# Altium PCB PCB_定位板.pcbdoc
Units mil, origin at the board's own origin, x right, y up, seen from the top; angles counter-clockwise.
Board outline 4260 x 2380 mil, 2 copper layers (Top Layer, Bottom Layer), stack 2.757 mil thick; 2 components, 2 nets, 2 pads, 2 vias.
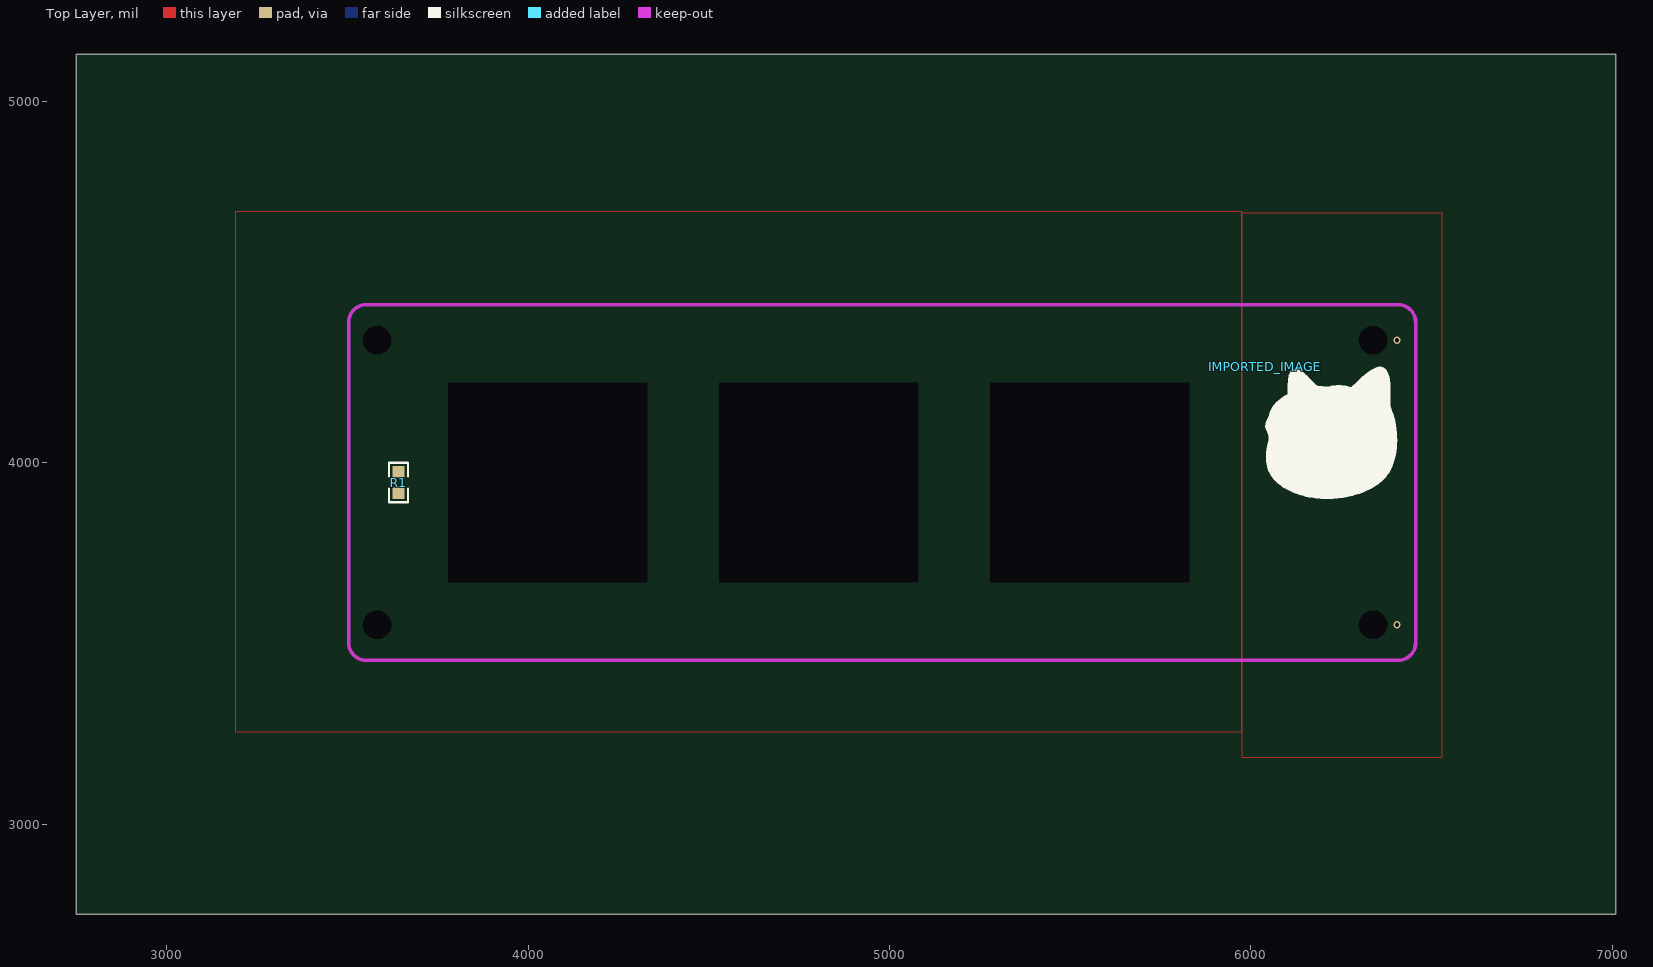
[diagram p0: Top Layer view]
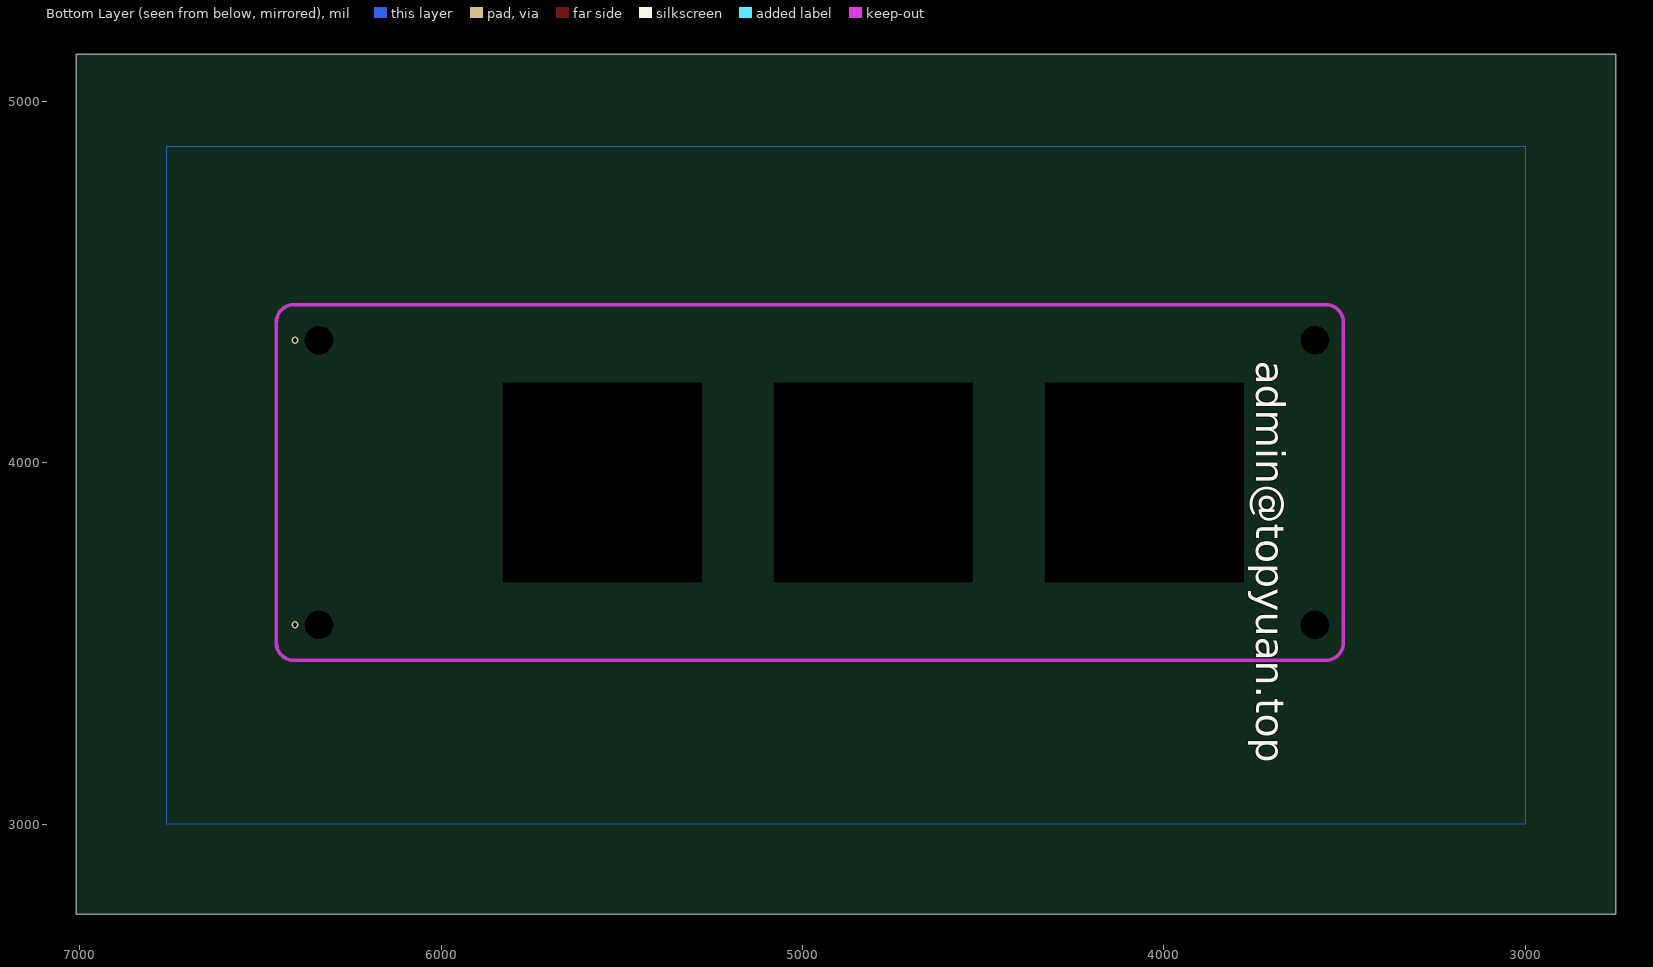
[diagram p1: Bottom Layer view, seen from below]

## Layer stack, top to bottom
Top Layer: signal copper 1.379
Bottom Layer: signal copper 1.378

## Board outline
7010,2750 2750,2750 2750,5130 7010,5130
cut-out: 3621.93,4338.7 ccw(c3582.56,4338.7) 3543.19,4338.7 ccw(c3582.56,4338.7)
cut-out: 3621.93,3551.3 ccw(c3582.56,3551.3) 3543.19,3551.3 ccw(c3582.56,3551.3)
cut-out: 6377.83,3551.3 ccw(c6338.46,3551.3) 6299.09,3551.3 ccw(c6338.46,3551.3)
cut-out: 6377.83,4338.7 ccw(c6338.46,4338.7) 6299.09,4338.7 ccw(c6338.46,4338.7)
cut-out: 3779.41,3669.41 4330.59,3669.41 4330.59,4220.59 3779.41,4220.59
cut-out: 4529.41,3669.41 5080.59,3669.41 5080.59,4220.59 4529.41,4220.59
cut-out: 5279.41,3669.41 5830.59,3669.41 5830.59,4220.59 5279.41,4220.59

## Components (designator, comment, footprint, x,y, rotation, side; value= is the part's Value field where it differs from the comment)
IMPORTED_IMAGE "IMPORTED_IMAGE" IMPORTED_IMAGE 6040,4265.27 r0 top
R1 "10K" R0603 3641.61,3945 r90 top

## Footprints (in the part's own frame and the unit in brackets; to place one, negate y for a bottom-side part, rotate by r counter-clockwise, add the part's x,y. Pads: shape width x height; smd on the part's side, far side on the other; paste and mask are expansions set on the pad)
IMPORTED_IMAGE [mil]
  silkscreen extent 0,-365 365,0
R0603 [mil]
  rect 31.75x34.02 smd: 1(-29.66,0) 2(29.66,0)
  silkscreen extent -55,-26 55,26

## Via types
v1: diameter 20, hole 11.81, Top Layer to Bottom Layer, 2 vias

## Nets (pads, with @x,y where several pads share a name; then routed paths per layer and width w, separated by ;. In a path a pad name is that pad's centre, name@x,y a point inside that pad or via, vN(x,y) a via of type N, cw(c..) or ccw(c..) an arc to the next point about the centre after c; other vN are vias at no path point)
GND: R1.1 R1.2
  other v1: 6405,3551.3 6405,4338.7
"": 

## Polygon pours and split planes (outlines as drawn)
GND on Top Layer (solid, remove dead copper, pour order 0): 3190,3255 5975,3255 5975,4695 3190,4695
GND on Top Layer (hatched 45Degree grid 30 track 10, remove dead copper, pour order 1): 5975,3185 6530,3185 6530,4690 5975,4690
GND on Bottom Layer (hatched 45Degree grid 30 track 10, remove dead copper, pour order 2): 3000,3000 6760,3000 6760,4875 3000,4875

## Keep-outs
Keep-Out Layer:
  lines w10 net "": 3503.82,3502.09 ccw(c3553.03,3502.09) 3553.03,3452.87 6407.36,3452.87 ccw(c6407.36,3502.09) 6456.57,3502.09 6456.57,4387.91 ccw(c6407.36,4387.91) 6407.36,4437.13 3553.03,4437.13 ccw(c3553.03,4387.91) 3503.82,4387.91 3503.82,3502.09

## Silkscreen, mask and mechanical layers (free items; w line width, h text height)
Bottom Silkscreen Layer:
  text "admin@topyuan.top" at 3744.63,4282.15 h79.3 r90
Top Solder Mask Layer:
  text "Developer" at 4054.44,4345.33 h89.2
  text "Coding" at 6219.15,3764.94 h133.8
  text "Hello world" at 4804.15,3561.24 h133.8
Bottom Solder Mask Layer:
  text "Yuan" at 4979.69,3557.26 h80.28
Mechanical 1:
  circle w1 net "": c3582.56,4338.7 r39.37
  circle w1 net "": c3582.56,3551.3 r39.37
  circle w1 net "": c6338.46,3551.3 r39.37
  circle w1 net "": c6338.46,4338.7 r39.37
  lines w1 net "": 3779.41,3669.41 4330.59,3669.41 4330.59,4220.59 3779.41,4220.59 3779.41,3669.41 ; 4529.41,3669.41 5080.59,3669.41 5080.59,4220.59 4529.41,4220.59 4529.41,3669.41 ; 5279.41,3669.41 5830.59,3669.41 5830.59,4220.59 5279.41,4220.59 5279.41,3669.41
